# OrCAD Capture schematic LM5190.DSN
size C
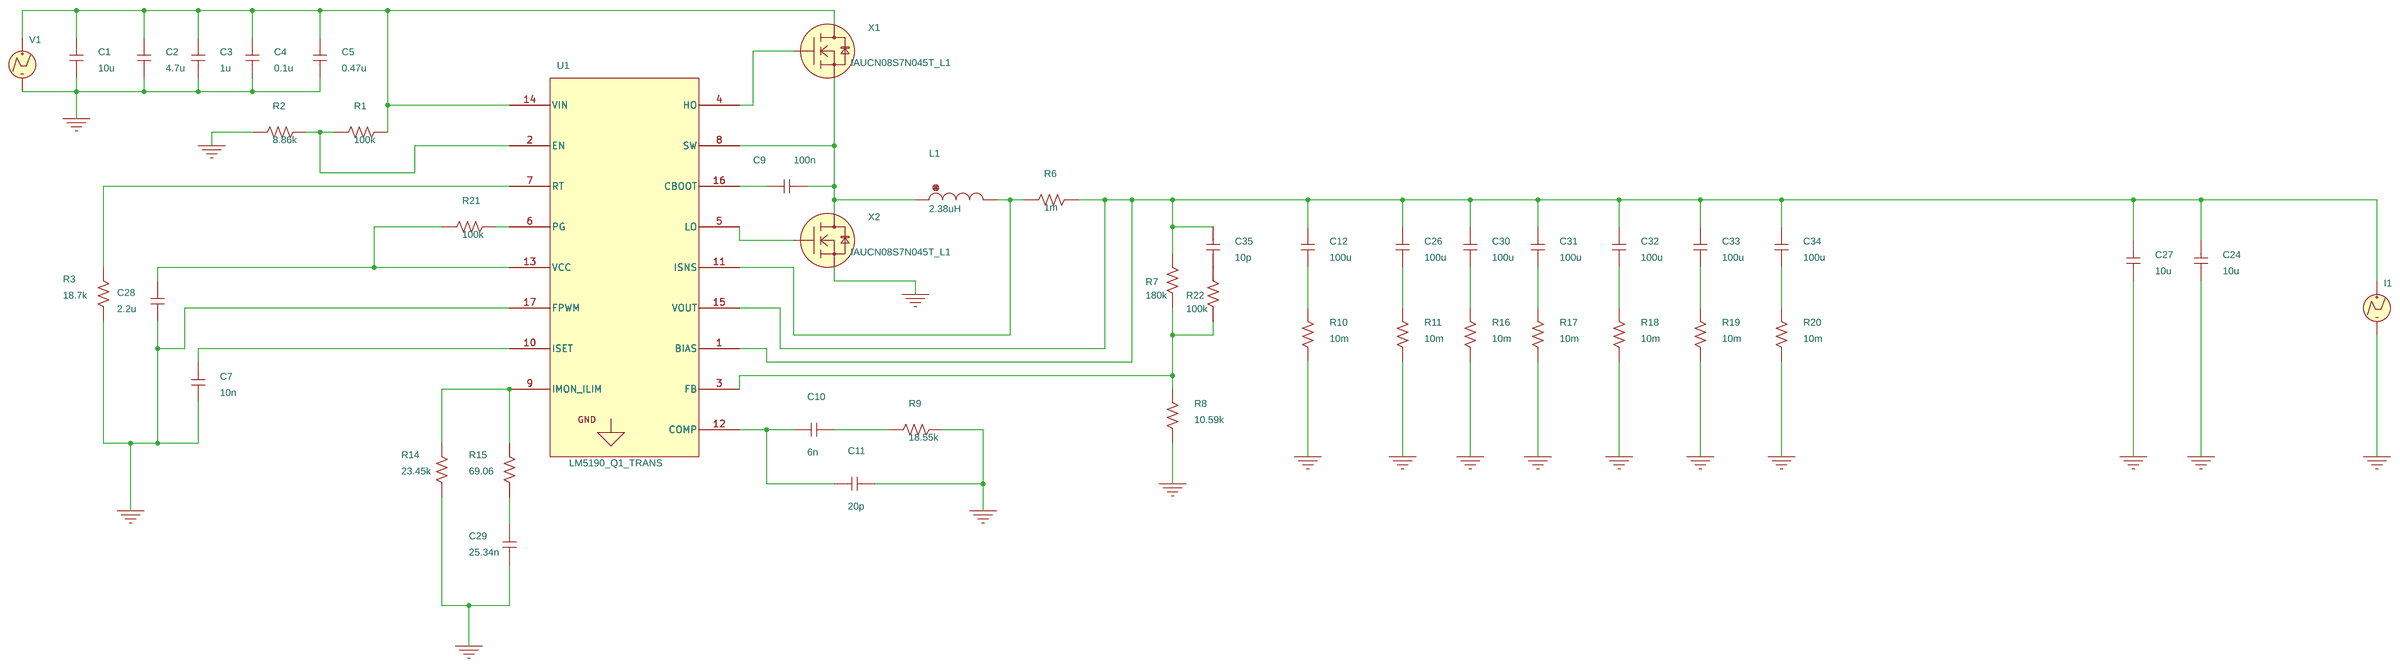
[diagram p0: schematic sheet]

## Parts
C1  10u  [RAD/CK05]
C2  4.7u  [RAD/CK05]
C3  1u  [RAD/CK05]
C4  0.1u  [RAD/CK05]
C5  0.47u  [RAD/CK05]
C7  10n  [RAD/CK05]
C9  100n  [RAD/CK05]
C10  6n  [RAD/CK05]
C11  20p  [RAD/CK05]
C12  100u  [RAD/CK05]
C24  10u  [RAD/CK05]
C26  100u  [RAD/CK05]
C27  10u  [RAD/CK05]
C28  2.2u  [RAD/CK05]
C29  25.34n  [RAD/CK05]
C30  100u  [RAD/CK05]
C31  100u  [RAD/CK05]
C32  100u  [RAD/CK05]
C33  100u  [RAD/CK05]
C34  100u  [RAD/CK05]
C35  10p  [RAD/CK05]
I1  IPWL_GENERIC
L1  2.38uH  [DISC/.350x.175/LS.200x.100/.034]
R1  100k  [AX/RC05]
R2  8.86k  [AX/RC05]
R3  18.7k  [AX/RC05]
R6  1m  [AX/RC05]
R7  180k  [AX/RC05]
R8  10.59k  [AX/RC05]
R9  18.55k  [AX/RC05]
R10  10m  [AX/RC05]
R11  10m  [AX/RC05]
R14  23.45k  [AX/RC05]
R15  69.06  [AX/RC05]
R16  10m  [AX/RC05]
R17  10m  [AX/RC05]
R18  10m  [AX/RC05]
R19  10m  [AX/RC05]
R20  10m  [AX/RC05]
R21  100k  [AX/RC05]
R22  100k  [AX/RC05]
U1  LM5190_Q1_TRANS
V1  VPWL_GENERIC
X1  IAUCN08S7N045T_L1
X2  IAUCN08S7N045T_L1

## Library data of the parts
C1-C5 C7 C9-C12 C24 C26-C35 = C
I1 = IPWL_GENERIC: AppProp: No_reps$POINTS_TYPE_PWL$0$0; FIRST_NPAIRS: 0m 0 3.2m 0 3.22m 8.7 3.4m 8.7 3.41m 35 3.61m 35 3.62m 8.7 4m 8.7 4.1m 0 4.3m 0 4.31m 35 4.51m 35 4.52m 0 5m 0 6m 0; PSpiceTemplate: I^@REFDES %+ %- ?DC|DC @DC| ?AC|AC @AC| PWL ?TSF|TIME_SCALE_FACTOR=@TSF| ?VSF|VALUE_SCALE_FACTOR=@VSF| ?REPEAT_VALUE| \n+ REPEAT FOR @REPEAT_VALUE| \n+ @FIRST_NPAIRS ?SECOND_NPAIRS|\n+ @SECOND_NPAIRS ?THIRD_NPAIRS/\n+ @THIRD_NPAIRS/| ?REPEAT_VALUE| \n+ ENDREPEAT|
L1 = L
R1-R3 R6-R11 R14-R22 = R
U1 = LM5190_Q1_TRANS
V1 = VPWL_GENERIC: AppProp: No_reps$POINTS_TYPE_PWL$0$0; FIRST_NPAIRS: 0 0 0.1m 48 5m 48 6m 48; PSpiceTemplate: V^@REFDES %+ %- ?DC|DC @DC| ?AC|AC @AC| PWL ?TSF|TIME_SCALE_FACTOR=@TSF| ?VSF|VALUE_SCALE_FACTOR=@VSF| ?REPEAT_VALUE| \n+ REPEAT FOR @REPEAT_VALUE| \n+ @FIRST_NPAIRS ?SECOND_NPAIRS|\n+ @SECOND_NPAIRS ?THIRD_NPAIRS/\n+ @THIRD_NPAIRS/| ?REPEAT_VALUE| \n+ ENDREPEAT|
X1 X2 = IAUCN08S7N045T_L1

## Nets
0: C1.1 C2.1 C3.1 C4.1 C5.1 C7.2 C11.1 C24.2 C27.2 C28.1 C29.1 I1.2(-) R2.1 R3.1 R8.1 R9.2 R10.1 R11.1 R14.1 R16.1 R17.1 R18.1 R19.1 R20.1 U1.17(FPWM) V1.2(-) X2.3(source)
N00215: C1.2 C2.2 C3.2 C4.2 C5.2 R1.2 U1.14(VIN) V1.1(+) X1.1(drain)
N00490: R1.1 R2.2 U1.2(EN)
N00607: R3.2 U1.7(RT)
N00908: C7.1 U1.10(ISET)
N01169: U1.4(HO) X1.2(gate)
N01219: C9.1 L1.1 U1.8(SW) X1.3(source) X2.1(drain)
N01254: C9.2 U1.16(CBOOT)
N01299: U1.5(LO) X2.2(gate)
N01429: L1.2 R6.1 U1.11(ISNS)
N01481: C12.1 C24.1 C26.1 C27.1 C30.1 C31.1 C32.1 C33.1 C34.1 C35.1 I1.1(+) R6.2 R7.2 U1.1(BIAS) U1.15(VOUT)
N01585: R7.1 R8.2 R22.1 U1.3(FB)
N01803: C10.2 C11.2 U1.12(COMP)
N01820: C10.1 R9.1
N02063: C12.2 R10.2
N23492: C26.2 R11.2
N29163: C28.2 R21.1 U1.13(VCC)
N29915: R14.2 R15.2 U1.9(IMON_ILIM)
N29933: C29.2 R15.1
N31971: C30.2 R16.2
N32325: C31.2 R17.2
N34445: C32.2 R18.2
N34658: C33.2 R19.2
N34872: C34.2 R20.2
N35058: R21.2 U1.6(PG)
N37222: C35.2 R22.2
